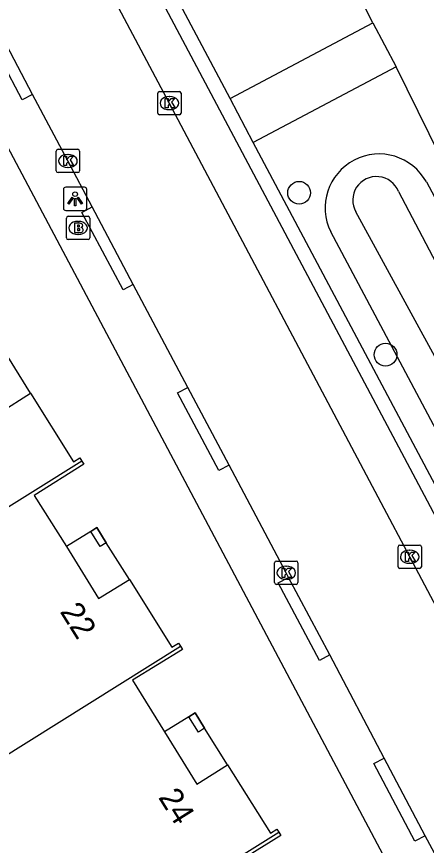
# Model space of a CAD drawing. Extents: x 158838 to 160074, y 386376 to 387776.
# Drawn here: x 159199.82 to 159217.42, y 387112.04 to 387147.63 of the extents above; entities that cross this region are included whole.
import ezdxf

# ---------------------------------------------------------------- set-up
doc = ezdxf.new("R2010")
doc.units = 0
for name, color, linetype in [('IMGEO_Berm_groen', 7, 'Continuous'), ('IMGEO_Boom', 7, 'Continuous'), ('IMGEO_Brandkraan', 7, 'Continuous'), ('IMGEO_Fietspad_gesloten', 7, 'Continuous'), ('IMGEO_Kolk', 7, 'Continuous'), ('IMGEO_Lichtpunt', 7, 'Continuous'), ('IMGEO_Pand', 7, 'Continuous'), ('IMGEO_Pand_nummerreeks', 7, 'Continuous'), ('IMGEO_Pand_overbouw', 7, 'Continuous'), ('IMGEO_Rijbaan_lokaal_open', 7, 'Continuous'), ('IMGEO_Voetpad_open', 7, 'Continuous'), ('IMGEO_Waterloop', 7, 'Continuous')]:
    doc.layers.add(name, color=color, linetype=linetype)

msp = doc.modelspace()

# ---------------------------------------------------------------- linework, layer by layer
at = {"layer": 'IMGEO_Berm_groen'}
for points in [[(159217.424, 387140.529), (159228.33, 387120.048)], [(159224.283, 387117.778), (159213.314, 387138.385)]]:
    msp.add_lwpolyline(points, dxfattribs=at)
msp.add_arc((159215.392, 387139.413), 2.318, 28.7851, 206.3129, dxfattribs=at)
at = {"layer": 'IMGEO_Boom'}
for centre in [(159211.957, 387140.065), (159215.667, 387133.114)]:
    msp.add_circle(centre, 0.489, dxfattribs=at)
at = {"layer": 'IMGEO_Brandkraan'}
for p, q in [((159201.966, 387138.13), (159201.966, 387138.982)), ((159202.041, 387139.056), (159202.893, 387139.056)), ((159202.454, 387138.836), (159202.479, 387138.836)), ((159202.967, 387138.982), (159202.967, 387138.13)), ((159202.477, 387138.276), (159202.452, 387138.276)), ((159202.893, 387138.056), (159202.041, 387138.056))]:
    msp.add_line(p, q, dxfattribs=at)
for points in [[(159201.966, 387138.13), (159201.966, 387138.982)], [(159202.041, 387139.056), (159202.893, 387139.056)], [(159202.967, 387138.982), (159202.967, 387138.13)], [(159202.314, 387138.756), (159202.314, 387138.356), (159202.527, 387138.356)], [(159202.545, 387138.756), (159202.314, 387138.756)], [(159202.493, 387138.675), (159202.439, 387138.675), (159202.439, 387138.599)], [(159202.439, 387138.599), (159202.492, 387138.599)], [(159202.501, 387138.523), (159202.439, 387138.523), (159202.439, 387138.442)], [(159202.439, 387138.442), (159202.501, 387138.442)], [(159202.893, 387138.056), (159202.041, 387138.056)]]:
    msp.add_lwpolyline(points, dxfattribs=at)
for centre, radius, start, end in [((159202.043, 387138.98), 0.0765, 91.552, 178.448), ((159202.043, 387138.98), 0.0765, 91.552, 178.448), ((159202.891, 387138.98), 0.0765, 1.552, 88.448), ((159202.891, 387138.98), 0.0765, 1.552, 88.448), ((159202.494, 387138.637), 0.0379, 267.8285, 90.9355), ((159202.502, 387138.482), 0.0404, 269.8759, 90.5077), ((159202.549, 387138.611), 0.145, 59.4692, 91.5367), ((159202.574, 387138.658), 0.0922, 285.5137, 58.1501), ((159202.579, 387138.466), 0.105, 301.3115, 78.989), ((159202.043, 387138.132), 0.0765, 181.552, 268.448), ((159202.043, 387138.132), 0.0765, 181.552, 268.448), ((159202.533, 387138.607), 0.251, 268.6676, 293.5347), ((159202.891, 387138.132), 0.0765, 271.552, 358.448), ((159202.891, 387138.132), 0.0765, 271.552, 358.448)]:
    msp.add_arc(centre, radius, start, end, dxfattribs=at)
for centre, major_axis, ratio, start_param, end_param in [((159202.453, 387138.556), (-0.387, 0.002), 0.722429, 4.712389, 7.853982), ((159202.478, 387138.556), (-0.39, 0.002), 0.717154, 1.570796, 4.712389)]:
    msp.add_ellipse(centre, major_axis=major_axis, ratio=ratio, start_param=start_param, end_param=end_param, dxfattribs=at)
at = {"layer": 'IMGEO_Fietspad_gesloten'}
for points in [[(159215.116, 387147.359), (159196.713, 387183.673)], [(159215.116, 387147.359), (159216.131, 387145.48)], [(159231.17, 387116.927), (159223.64, 387131.346), (159223.201, 387131.121), (159216.131, 387145.48)]]:
    msp.add_lwpolyline(points, dxfattribs=at)
at = {"layer": 'IMGEO_Kolk'}
for p, q in [((159205.887, 387143.488), (159205.887, 387144.34)), ((159205.962, 387144.414), (159206.814, 387144.414)), ((159206.375, 387144.194), (159206.4, 387144.194)), ((159206.888, 387144.34), (159206.888, 387143.488)), ((159206.398, 387143.634), (159206.373, 387143.634)), ((159206.814, 387143.414), (159205.962, 387143.414)), ((159201.53, 387141.005), (159201.53, 387141.857)), ((159201.605, 387141.931), (159202.457, 387141.931)), ((159202.018, 387141.711), (159202.043, 387141.711)), ((159202.531, 387141.857), (159202.531, 387141.005)), ((159202.041, 387141.151), (159202.016, 387141.151)), ((159202.457, 387140.931), (159201.605, 387140.931)), ((159216.205, 387124.01), (159216.205, 387124.862)), ((159216.28, 387124.936), (159217.132, 387124.936)), ((159216.693, 387124.716), (159216.718, 387124.716)), ((159217.206, 387124.862), (159217.206, 387124.01)), ((159210.979, 387124.252), (159211.831, 387124.252)), ((159210.904, 387123.326), (159210.904, 387124.178)), ((159211.392, 387124.032), (159211.417, 387124.032)), ((159211.905, 387124.178), (159211.905, 387123.326)), ((159217.132, 387123.936), (159216.28, 387123.936)), ((159216.716, 387124.156), (159216.691, 387124.156)), ((159211.831, 387123.252), (159210.979, 387123.252)), ((159211.415, 387123.472), (159211.39, 387123.472))]:
    msp.add_line(p, q, dxfattribs=at)
for points in [[(159205.887, 387143.488), (159205.887, 387144.34)], [(159205.962, 387144.414), (159206.814, 387144.414)], [(159206.888, 387144.34), (159206.888, 387143.488)], [(159206.208, 387144.114), (159206.331, 387144.114), (159206.331, 387143.963), (159206.461, 387144.114), (159206.625, 387144.114), (159206.479, 387143.963), (159206.632, 387143.714), (159206.48, 387143.714), (159206.395, 387143.878), (159206.331, 387143.811), (159206.331, 387143.714), (159206.208, 387143.714), (159206.208, 387144.114)], [(159206.814, 387143.414), (159205.962, 387143.414)], [(159201.53, 387141.005), (159201.53, 387141.857)], [(159201.605, 387141.931), (159202.457, 387141.931)], [(159202.531, 387141.857), (159202.531, 387141.005)], [(159201.851, 387141.631), (159201.974, 387141.631), (159201.974, 387141.48), (159202.104, 387141.631), (159202.268, 387141.631), (159202.122, 387141.48), (159202.275, 387141.231), (159202.123, 387141.231), (159202.038, 387141.395), (159201.974, 387141.328), (159201.974, 387141.231), (159201.851, 387141.231), (159201.851, 387141.631)], [(159202.457, 387140.931), (159201.605, 387140.931)], [(159216.205, 387124.01), (159216.205, 387124.862)], [(159216.28, 387124.936), (159217.132, 387124.936)], [(159216.526, 387124.636), (159216.649, 387124.636), (159216.649, 387124.485), (159216.779, 387124.636), (159216.943, 387124.636), (159216.797, 387124.485), (159216.95, 387124.236), (159216.798, 387124.236), (159216.713, 387124.4), (159216.649, 387124.333), (159216.649, 387124.236), (159216.526, 387124.236), (159216.526, 387124.636)], [(159217.206, 387124.862), (159217.206, 387124.01)], [(159210.979, 387124.252), (159211.831, 387124.252)], [(159210.904, 387123.326), (159210.904, 387124.178)], [(159211.225, 387123.952), (159211.348, 387123.952), (159211.348, 387123.801), (159211.478, 387123.952), (159211.642, 387123.952), (159211.496, 387123.801), (159211.649, 387123.552), (159211.497, 387123.552), (159211.412, 387123.716), (159211.348, 387123.649), (159211.348, 387123.552), (159211.225, 387123.552), (159211.225, 387123.952)], [(159211.905, 387124.178), (159211.905, 387123.326)], [(159217.132, 387123.936), (159216.28, 387123.936)], [(159211.831, 387123.252), (159210.979, 387123.252)]]:
    msp.add_lwpolyline(points, dxfattribs=at)
for centre, start, end in [((159205.964, 387144.338), 91.552, 178.448), ((159205.964, 387144.338), 91.552, 178.448), ((159206.812, 387144.338), 1.552, 88.448), ((159206.812, 387144.338), 1.552, 88.448), ((159205.964, 387143.49), 181.552, 268.448), ((159205.964, 387143.49), 181.552, 268.448), ((159206.812, 387143.49), 271.552, 358.448), ((159206.812, 387143.49), 271.552, 358.448), ((159201.607, 387141.855), 91.552, 178.448), ((159201.607, 387141.855), 91.552, 178.448), ((159202.455, 387141.855), 1.552, 88.448), ((159202.455, 387141.855), 1.552, 88.448), ((159201.607, 387141.007), 181.552, 268.448), ((159201.607, 387141.007), 181.552, 268.448), ((159202.455, 387141.007), 271.552, 358.448), ((159202.455, 387141.007), 271.552, 358.448), ((159216.282, 387124.86), 91.552, 178.448), ((159216.282, 387124.86), 91.552, 178.448), ((159217.13, 387124.86), 1.552, 88.448), ((159217.13, 387124.86), 1.552, 88.448), ((159210.981, 387124.176), 91.552, 178.448), ((159210.981, 387124.176), 91.552, 178.448), ((159211.829, 387124.176), 1.552, 88.448), ((159211.829, 387124.176), 1.552, 88.448), ((159216.282, 387124.012), 181.552, 268.448), ((159216.282, 387124.012), 181.552, 268.448), ((159217.13, 387124.012), 271.552, 358.448), ((159217.13, 387124.012), 271.552, 358.448), ((159210.981, 387123.328), 181.552, 268.448), ((159210.981, 387123.328), 181.552, 268.448), ((159211.829, 387123.328), 271.552, 358.448), ((159211.829, 387123.328), 271.552, 358.448)]:
    msp.add_arc(centre, 0.0765, start, end, dxfattribs=at)
for centre, major_axis, ratio, start_param, end_param in [((159206.374, 387143.914), (-0.387, 0.002), 0.722429, 4.712389, 7.853982), ((159206.399, 387143.914), (-0.39, 0.002), 0.717154, 1.570796, 4.712389), ((159202.017, 387141.431), (-0.387, 0.002), 0.722429, 4.712389, 7.853982), ((159202.042, 387141.431), (-0.39, 0.002), 0.717154, 1.570796, 4.712389), ((159216.692, 387124.436), (-0.387, 0.002), 0.722429, 4.712389, 7.853982), ((159216.717, 387124.436), (-0.39, 0.002), 0.717154, 1.570796, 4.712389), ((159211.391, 387123.752), (-0.387, 0.002), 0.722429, 4.712389, 7.853982), ((159211.416, 387123.752), (-0.39, 0.002), 0.717154, 1.570796, 4.712389)]:
    msp.add_ellipse(centre, major_axis=major_axis, ratio=ratio, start_param=start_param, end_param=end_param, dxfattribs=at)
at = {"layer": 'IMGEO_Lichtpunt'}
for p, q in [((159202.741, 387140.303), (159201.933, 387140.303)), ((159202.741, 387140.303), (159201.933, 387140.303)), ((159201.839, 387140.208), (159201.839, 387139.401)), ((159201.839, 387140.208), (159201.839, 387139.401)), ((159202.835, 387139.401), (159202.835, 387140.208)), ((159202.835, 387139.401), (159202.835, 387140.208)), ((159201.933, 387139.307), (159202.741, 387139.307)), ((159201.933, 387139.307), (159202.741, 387139.307))]:
    msp.add_line(p, q, dxfattribs=at)
for points in [[(159202.213, 387139.872), (159202.252, 387139.844), (159202.064, 387139.582), (159202.026, 387139.609), (159202.213, 387139.872)], [(159202.315, 387139.824), (159202.362, 387139.824), (159202.362, 387139.502), (159202.315, 387139.502), (159202.315, 387139.824)], [(159202.425, 387139.844), (159202.463, 387139.871), (159202.65, 387139.609), (159202.611, 387139.581), (159202.425, 387139.844)]]:
    msp.add_lwpolyline(points, dxfattribs=at)
msp.add_circle((159202.338, 387140.006), 0.0994, dxfattribs=at)
for centre, start, end in [((159201.933, 387140.208), 90, 180), ((159201.933, 387140.208), 90, 180), ((159202.741, 387140.208), 0, 90), ((159202.741, 387140.208), 0, 90), ((159201.933, 387139.401), 180, 270), ((159201.933, 387139.401), 180, 270), ((159202.741, 387139.401), 270, 0), ((159202.741, 387139.401), 270, 360)]:
    msp.add_arc(centre, 0.0946, start, end, dxfattribs=at)
at = {"layer": 'IMGEO_Pand'}
for points in [[(159198.406, 387136.526), (159198.491, 387136.39), (159196.356, 387135.062), (159197.721, 387132.868), (159199.103, 387130.627), (159200.428, 387131.455), (159202.264, 387128.509), (159202.544, 387128.684), (159202.629, 387128.548)], [(159202.629, 387128.548), (159192.211, 387122.033)], [(159202.629, 387128.548), (159202.714, 387128.412), (159200.584, 387127.072), (159201.966, 387124.874), (159203.347, 387122.641), (159204.667, 387123.466), (159206.495, 387120.555), (159206.773, 387120.73), (159206.858, 387120.595)], [(159203.006, 387125.528), (159203.268, 387125.693), (159203.678, 387125.041), (159203.415, 387124.876), (159203.006, 387125.528)], [(159196.432, 387114.069), (159206.858, 387120.595)], [(159206.858, 387120.595), (159206.943, 387120.46), (159204.804, 387119.145), (159206.171, 387116.92), (159207.566, 387114.677), (159208.886, 387115.502), (159210.724, 387112.57), (159211.004, 387112.746), (159211.089, 387112.61)], [(159207.225, 387117.568), (159207.489, 387117.73), (159207.898, 387117.078), (159207.635, 387116.913), (159207.225, 387117.568)], [(159200.658, 387106.098), (159211.089, 387112.61)], [(159211.089, 387112.61), (159211.174, 387112.474), (159209.03, 387111.133), (159210.408, 387108.929), (159211.8, 387106.699), (159213.121, 387107.524), (159214.954, 387104.604), (159215.233, 387104.779), (159215.318, 387104.644)]]:
    msp.add_lwpolyline(points, dxfattribs=at)
at = {"layer": 'IMGEO_Pand_overbouw'}
for points in [[(159199.444, 387133.034), (159199.037, 387133.687), (159198.774, 387133.523), (159197.721, 387132.868), (159199.103, 387130.627), (159200.428, 387131.455)], [(159203.678, 387125.041), (159203.268, 387125.693), (159203.006, 387125.528), (159201.966, 387124.874), (159203.347, 387122.641), (159204.667, 387123.466)], [(159207.898, 387117.078), (159207.489, 387117.73), (159207.225, 387117.568), (159206.171, 387116.92), (159207.566, 387114.677), (159208.886, 387115.502)]]:
    msp.add_lwpolyline(points, close=True, dxfattribs=at)
at = {"layer": 'IMGEO_Rijbaan_lokaal_open'}
for points in [[(159185.962, 387182.529), (159186.994, 387180.354), (159195.093, 387165.124), (159206.383, 387143.913), (159215.465, 387126.768), (159216.713, 387124.427), (159225.399, 387108.034), (159237.811, 387084.633), (159248.115, 387065.172), (159257.979, 387046.591), (159267.363, 387028.878), (159268.082, 387027.672)], [(159200.511, 387144.285), (159198.74, 387147.617)], [(159203.075, 387139.456), (159202.028, 387141.432), (159200.511, 387144.285)], [(159204.837, 387136.129), (159203.075, 387139.456)], [(159207.181, 387131.704), (159204.837, 387136.129)], [(159208.952, 387128.372), (159207.181, 387131.704)], [(159211.503, 387123.554), (159211.403, 387123.752), (159208.952, 387128.372)], [(159213.276, 387120.222), (159211.503, 387123.554)], [(159215.613, 387115.79), (159213.276, 387120.222)], [(159217.374, 387112.457), (159215.613, 387115.79)], [(159219.95, 387107.637), (159219.855, 387107.834), (159217.374, 387112.457)]]:
    msp.add_lwpolyline(points, dxfattribs=at)
at = {"layer": 'IMGEO_Voetpad_open'}
for points in [[(159208.994, 387144.108), (159187.621, 387184.289)], [(159188.607, 387181.119), (159217.085, 387127.542), (159268.384, 387030.839), (159268.404, 387030.804), (159268.439, 387030.73), (159268.468, 387030.653), (159268.49, 387030.574), (159268.504, 387030.493), (159268.512, 387030.411), (159268.512, 387030.329), (159268.504, 387030.247), (159268.49, 387030.166), (159268.468, 387030.087), (159268.089, 387028.603), (159268.053, 387028.439), (159268.033, 387028.272), (159268.027, 387028.103), (159268.036, 387027.936), (159268.061, 387027.769), (159268.082, 387027.672)], [(159261.184, 387025.643), (159192.812, 387154.528), (159184.858, 387169.495), (159180.565, 387177.574), (159180.465, 387177.724), (159180.352, 387177.865), (159180.227, 387177.995), (159180.091, 387178.113), (159179.944, 387178.219), (159179.789, 387178.311), (159179.627, 387178.389), (159179.458, 387178.452), (159179.284, 387178.5), (159179.106, 387178.532), (159178.926, 387178.548), (159178.746, 387178.548), (159178.566, 387178.532), (159178.388, 387178.5), (159178.214, 387178.452), (159178.045, 387178.389), (159177.883, 387178.311)], [(159200.511, 387144.285), (159200.07, 387144.051), (159198.299, 387147.383), (159198.74, 387147.617)], [(159208.994, 387144.108), (159215.116, 387147.359)], [(159216.131, 387145.48), (159209.987, 387142.226)], [(159209.987, 387142.226), (159208.994, 387144.108)], [(159225.151, 387113.68), (159209.987, 387142.226)], [(159204.837, 387136.129), (159204.396, 387135.895), (159202.633, 387139.222), (159203.075, 387139.456)], [(159208.952, 387128.372), (159208.511, 387128.138), (159206.74, 387131.47), (159207.181, 387131.704)], [(159213.276, 387120.222), (159212.835, 387119.988), (159211.062, 387123.32), (159211.503, 387123.554)], [(159217.374, 387112.457), (159216.932, 387112.224), (159215.171, 387115.557), (159215.613, 387115.79)]]:
    msp.add_lwpolyline(points, dxfattribs=at)
at = {"layer": 'IMGEO_Waterloop'}
msp.add_lwpolyline([(159216.221, 387140.115), (159227.617, 387118.452), (159226.015, 387117.63), (159221.436, 387126.357), (159214.393, 387139.242)], dxfattribs=at)
msp.add_arc((159215.275, 387139.746), 1.016, 21.3089, 209.7467, dxfattribs=at)

# ---------------------------------------------------------------- texts
at = {"layer": 'IMGEO_Pand_nummerreeks'}
for s, rotation, p in [('22', 302.1313, (159201.663, 387122.082)), ('24', 302.0854, (159205.889, 387114.108))]:
    msp.add_text(s, height=1, rotation=rotation, dxfattribs=at).set_placement(p)

doc.saveas('drawing.dxf')
